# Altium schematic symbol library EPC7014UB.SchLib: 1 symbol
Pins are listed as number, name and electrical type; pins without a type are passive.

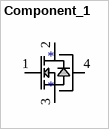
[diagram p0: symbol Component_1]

## Component_1
designator *
Part Number: EPC7014UB
footprint EPC7014UB (UB package Footprint used for surface mounting devices)
pins: 1, 2, 3, 4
